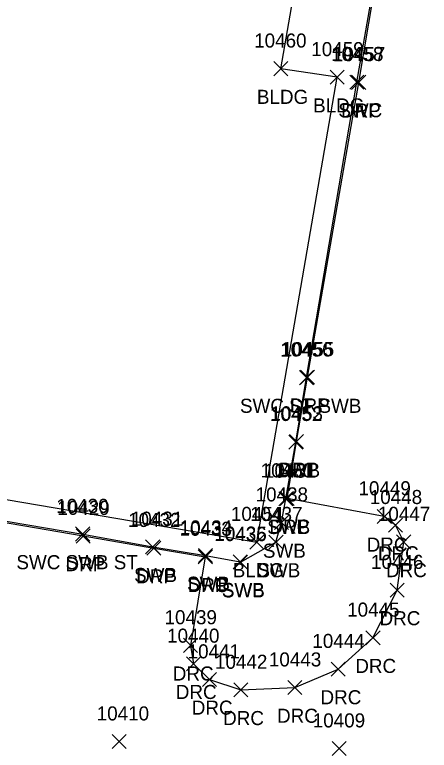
# Model space of a CAD drawing. Extents: x 1769141 to 1770911, y 735471 to 741449.
# Drawn here: x 1770437.1 to 1770496, y 738669.1 to 738773.6 of the extents above; entities that cross this region are included whole.
import ezdxf

# ---------------------------------------------------------------- set-up
doc = ezdxf.new("R2010")
doc.units = 0
for name, color, linetype in [('L_A', 7, 'Continuous'), ('L_I', 7, 'Continuous'), ('L_TIC', 7, 'Continuous'), ('LBC', 7, 'Continuous'), ('R_A', 7, 'Continuous'), ('R_I', 7, 'Continuous'), ('R_TIC', 7, 'Continuous'), ('RDP', 7, 'Continuous'), ('RSW', 7, 'Continuous')]:
    doc.layers.add(name, color=color, linetype=linetype)

msp = doc.modelspace()

# ---------------------------------------------------------------- linework, layer by layer
at = {"layer": 'L_TIC'}
for points in [[(1770473.89, 738764.91), (1770475.89, 738766.91)], [(1770475.89, 738764.91), (1770473.89, 738766.91)], [(1770481.87, 738763.69), (1770483.87, 738765.69)], [(1770483.87, 738763.69), (1770481.87, 738765.69)], [(1770470.46, 738697.65), (1770472.46, 738699.65)], [(1770472.46, 738697.65), (1770470.46, 738699.65)], [(1770450.93, 738669.3), (1770452.93, 738671.3)], [(1770452.93, 738669.3), (1770450.93, 738671.3)], [(1770482.17, 738668.31), (1770484.17, 738670.31)], [(1770484.17, 738668.31), (1770482.17, 738670.31)]]:
    msp.add_lwpolyline(points, dxfattribs=at)
at = {"layer": 'LBC'}
msp.add_lwpolyline([(1770355.73, 738726.42), (1770369.22, 738724.05), (1770376.65, 738722.75), (1770406.47, 738717.79), (1770405, 738709.95), (1770471.46, 738698.65), (1770482.87, 738764.69), (1770474.89, 738765.91), (1770480.75, 738799.69), (1770482.75, 738812.2), (1770482.74, 738812.43), (1770446.14, 738818.58), (1770408.11, 738825.21), (1770373.6, 738831.13), (1770373.19, 738830.95), (1770367.66, 738799.21), (1770361.53, 738763.21), (1770355.28, 738727.34)], dxfattribs=at)
at = {"layer": 'R_TIC'}
for points in [[(1770484.68, 738763.01), (1770486.68, 738765.01)], [(1770486.68, 738763.01), (1770484.68, 738765.01)], [(1770484.93, 738762.97), (1770486.93, 738764.97)], [(1770486.93, 738762.97), (1770484.93, 738764.97)], [(1770477.52, 738721.01), (1770479.52, 738723.01)], [(1770479.52, 738721.01), (1770477.52, 738723.01)], [(1770477.52, 738721.01), (1770479.52, 738723.01)], [(1770479.52, 738721.01), (1770477.52, 738723.01)], [(1770477.68, 738721.06), (1770479.68, 738723.06)], [(1770479.68, 738721.06), (1770477.68, 738723.06)], [(1770476, 738711.85), (1770478, 738713.85)], [(1770478, 738711.85), (1770476, 738713.85)], [(1770476.09, 738711.94), (1770478.09, 738713.94)], [(1770478.09, 738711.94), (1770476.09, 738713.94)], [(1770474.58, 738703.79), (1770476.58, 738705.79)], [(1770476.58, 738703.79), (1770474.58, 738705.79)], [(1770474.77, 738703.84), (1770476.77, 738705.84)], [(1770476.77, 738703.84), (1770474.77, 738705.84)], [(1770474.77, 738703.84), (1770476.77, 738705.84)], [(1770476.77, 738703.84), (1770474.77, 738705.84)], [(1770488.57, 738701.29), (1770490.57, 738703.29)], [(1770490.57, 738701.29), (1770488.57, 738703.29)], [(1770473.97, 738700.42), (1770475.97, 738702.42)], [(1770475.97, 738700.42), (1770473.97, 738702.42)], [(1770490.17, 738700.05), (1770492.17, 738702.05)], [(1770492.17, 738700.05), (1770490.17, 738702.05)], [(1770445.75, 738698.79), (1770447.75, 738700.79)], [(1770447.75, 738698.79), (1770445.75, 738700.79)], [(1770445.75, 738698.79), (1770447.75, 738700.79)], [(1770447.75, 738698.79), (1770445.75, 738700.79)], [(1770445.82, 738698.51), (1770447.82, 738700.51)], [(1770447.82, 738698.51), (1770445.82, 738700.51)], [(1770455.69, 738696.97), (1770457.69, 738698.97)], [(1770457.69, 738696.97), (1770455.69, 738698.97)], [(1770473.19, 738697.64), (1770475.19, 738699.64)], [(1770475.19, 738697.64), (1770473.19, 738699.64)], [(1770491.32, 738697.66), (1770493.32, 738699.66)], [(1770493.32, 738697.66), (1770491.32, 738699.66)], [(1770455.86, 738696.79), (1770457.86, 738698.79)], [(1770457.86, 738696.79), (1770455.86, 738698.79)], [(1770463.16, 738695.54), (1770465.16, 738697.54)], [(1770465.16, 738695.54), (1770463.16, 738697.54)], [(1770463.16, 738695.54), (1770465.16, 738697.54)], [(1770465.16, 738695.54), (1770463.16, 738697.54)], [(1770463.2, 738695.73), (1770465.2, 738697.73)], [(1770465.2, 738695.73), (1770463.2, 738697.73)], [(1770468.12, 738694.85), (1770470.12, 738696.85)], [(1770470.12, 738694.85), (1770468.12, 738696.85)], [(1770468.15, 738694.78), (1770470.15, 738696.78)], [(1770470.15, 738694.78), (1770468.15, 738696.78)], [(1770490.4, 738690.83), (1770492.4, 738692.83)], [(1770492.4, 738690.83), (1770490.4, 738692.83)], [(1770486.96, 738684.05), (1770488.96, 738686.05)], [(1770488.96, 738684.05), (1770486.96, 738686.05)], [(1770461.05, 738682.97), (1770463.05, 738684.97)], [(1770463.05, 738682.97), (1770461.05, 738684.97)], [(1770461.48, 738680.35), (1770463.48, 738682.35)], [(1770463.48, 738680.35), (1770461.48, 738682.35)], [(1770482.02, 738679.6), (1770484.02, 738681.6)], [(1770484.02, 738679.6), (1770482.02, 738681.6)], [(1770463.75, 738678.12), (1770465.75, 738680.12)], [(1770465.75, 738678.12), (1770463.75, 738680.12)], [(1770468.2, 738676.64), (1770470.2, 738678.64)], [(1770470.2, 738676.64), (1770468.2, 738678.64)], [(1770475.85, 738676.97), (1770477.85, 738678.97)], [(1770477.85, 738676.97), (1770475.85, 738678.97)]]:
    msp.add_lwpolyline(points, dxfattribs=at)
at = {"layer": 'RDP'}
for points in [[(1770475.77, 738704.84), (1770477.09, 738712.94), (1770478.68, 738722.06), (1770485.93, 738763.97), (1770491.54, 738797.17), (1770493.83, 738811.35), (1770483.05, 738813.07)], [(1770367.74, 738713.19), (1770378.07, 738711.32), (1770409.82, 738705.96), (1770416.23, 738704.75), (1770422.72, 738703.67), (1770446.82, 738699.51), (1770456.86, 738697.79), (1770464.16, 738696.54)], [(1770464.16, 738696.54), (1770462.05, 738683.97), (1770462.48, 738681.35), (1770464.75, 738679.12), (1770469.2, 738677.64), (1770476.85, 738677.97), (1770483.02, 738680.6), (1770487.96, 738685.05), (1770491.4, 738691.83), (1770492.32, 738698.66), (1770491.17, 738701.05), (1770489.57, 738702.29), (1770475.77, 738704.84)]]:
    msp.add_lwpolyline(points, dxfattribs=at)
at = {"layer": 'RSW'}
for points in [[(1770478.52, 738722.01), (1770485.68, 738764.01), (1770491.5, 738797.29), (1770493.83, 738811.35)], [(1770355.73, 738726.42), (1770354.08, 738715.46), (1770367.74, 738713.19), (1770378.05, 738711.45), (1770409.68, 738706.11), (1770416.13, 738704.93), (1770422.72, 738703.84), (1770446.75, 738699.79)], [(1770446.75, 738699.79), (1770456.69, 738697.97), (1770464.2, 738696.73), (1770469.12, 738695.85), (1770469.15, 738695.78), (1770474.19, 738698.64), (1770474.97, 738701.42), (1770475.58, 738704.79), (1770477, 738712.85), (1770478.52, 738722.01)]]:
    msp.add_lwpolyline(points, dxfattribs=at)

# ---------------------------------------------------------------- texts
at = {"layer": 'L_A'}
for p in [(1770471.48, 738760.91), (1770479.46, 738759.69), (1770468.05, 738693.65)]:
    msp.add_text('BLDG', height=2, dxfattribs=at).set_placement(p)
at = {"layer": 'L_I'}
for s, p in [('10460', (1770471.09, 738768.91)), ('10459', (1770479.2, 738767.69)), ('10454', (1770467.79, 738701.65)), ('10410', (1770448.74, 738673.3)), ('10409', (1770479.41, 738672.31))]:
    msp.add_text(s, height=2, dxfattribs=at).set_placement(p)
at = {"layer": 'R_A'}
for s, p in [('SWC', (1770483.04, 738759.01)), ('DRP', (1770483.42, 738758.97)), ('SWC ST SWB', (1770469.08, 738717.01)), ('SWC ST SWB', (1770469.08, 738717.01)), ('DRP', (1770476.17, 738717.06)), ('SWB', (1770474.36, 738707.85)), ('DRP', (1770474.58, 738707.94)), ('SWB', (1770472.95, 738699.79)), ('DRC', (1770473.25, 738699.84)), ('DRP', (1770473.25, 738699.84)), ('DRC', (1770487.06, 738697.29)), ('SWB', (1770472.33, 738696.42)), ('DRC', (1770488.66, 738696.05)), ('SWC SWB ST', (1770437.34, 738694.79)), ('SWC SWB ST', (1770437.34, 738694.79)), ('DRP', (1770444.31, 738694.51)), ('SWB', (1770454.05, 738692.97)), ('DRP', (1770454.35, 738692.79)), ('SWB', (1770471.55, 738693.64)), ('DRC', (1770489.81, 738693.66)), ('SWB', (1770461.56, 738691.73)), ('DRC', (1770461.65, 738691.54)), ('DRP', (1770461.65, 738691.54)), ('SWB', (1770466.49, 738690.85)), ('SWB', (1770466.52, 738690.78)), ('DRC', (1770488.89, 738686.83)), ('DRC', (1770485.45, 738680.05)), ('DRC', (1770459.54, 738678.97)), ('DRC', (1770459.97, 738676.35)), ('DRC', (1770480.51, 738675.6)), ('DRC', (1770462.24, 738674.12)), ('DRC', (1770474.34, 738672.97)), ('DRC', (1770466.69, 738672.64))]:
    msp.add_text(s, height=2, dxfattribs=at).set_placement(p)
at = {"layer": 'R_I'}
for s, p in [('10458', (1770482.01, 738767.01)), ('10457', (1770482.26, 738766.97)), ('10456', (1770474.79, 738725.01)), ('10456', (1770474.79, 738725.01)), ('10455', (1770475.02, 738725.06)), ('10452', (1770473.33, 738715.85)), ('10453', (1770473.42, 738715.94)), ('10450', (1770472.01, 738707.84)), ('10450', (1770472.01, 738707.84)), ('10451', (1770472.48, 738707.79)), ('10449', (1770485.9, 738705.29)), ('10438', (1770471.3, 738704.42)), ('10448', (1770487.5, 738704.05)), ('10430', (1770443, 738702.79)), ('10430', (1770443, 738702.79)), ('10429', (1770443.15, 738702.51)), ('10437', (1770470.52, 738701.64)), ('10447', (1770488.65, 738701.66)), ('10432', (1770453.19, 738700.79)), ('10431', (1770453.58, 738700.97)), ('10433', (1770460.49, 738699.54)), ('10433', (1770460.49, 738699.54)), ('10434', (1770460.53, 738699.73)), ('10436', (1770465.43, 738698.78)), ('10435', (1770465.45, 738698.85)), ('10446', (1770487.68, 738694.83)), ('10445', (1770484.29, 738688.05)), ('10439', (1770458.37, 738686.97)), ('10440', (1770458.73, 738684.35)), ('10444', (1770479.35, 738683.6)), ('10441', (1770461.65, 738682.12)), ('10442', (1770465.53, 738680.64)), ('10443', (1770473.18, 738680.97))]:
    msp.add_text(s, height=2, dxfattribs=at).set_placement(p)

doc.saveas('drawing.dxf')
